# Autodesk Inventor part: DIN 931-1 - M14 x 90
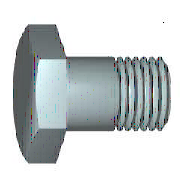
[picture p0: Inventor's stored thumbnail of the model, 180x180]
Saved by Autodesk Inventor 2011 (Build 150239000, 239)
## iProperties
Created: 2010-02
Part Number: DIN 931-1 - M14 x 90
Material: Steel, Mild
Description: Hex-Head Bolt
Document SubType Name: Modeling
Standard: DIN 931-1
Designer: PC
Standard Revision: 2001
Standards Organization: DIN
Language: en-US
Size Designation: M14 x 90
Categories: <MemberInstance><Categories><Category DisplayName="Fasteners" InternalName="e4da775c-781d-43d5-af7c-5136215cf5a6" Mnemonic="FSTN"><Category DisplayName="Bolts"
Density: 1 g/cm^3
IsCustomPart: 0
Author: PC
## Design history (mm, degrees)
workplane "Work Plane1"
revolve "Body" stored, may be unused: angle "d12" = 90 deg
sketch "Sketch2"
  geometry: L1 (0, 12.702)-(11, 6.351); L2 (11, 6.351)-(11, -6.351); L3 (11, -6.351)-(0, -12.702); L4 (0, -12.702)-(-11, -6.351); L5 (-11, -6.351)-(-11, 6.351); L6 (-11, 6.351)-(0, 12.702); 2 further points
  constraints: 12 end point, 1 coincident, 1 vertical, 11 other
  dimensions: "d11" = 22 distance between parallel lines of L5 L2 (= SW)
extrude "Head" join sketch "Sketch2" distance "d3" = 8.2 (= KOH - SD); taper "d4" = 0 deg
revolve "Chamfer1" stored, may be unused: angle "d21" = 90 deg
body "Solid1"
feature "Thread" dims "d15" = 34 (= GEL), "d16" = 0
chamfer "Chamfer2" distance "d6" = 1.2269 (= -0.5 x SPD + 0.5 x GD); stored, may be unused: second distance "d7" = 1.227 (computed from GUL), angle "d55" = 45 deg
sketch "Sketch1"
  geometry: L1 (0, 10.25)-(0, 7); L2 (56, 7)-(90, 7); L3 (90, 7)-(90, 0); L4 (90, 0)-(-0.6, 0); L5 (-18.72, 0)-(108.12, 0) reference; L6 (-0.6, 0)-(-0.6, 10.25); L7 (-0.6, 10.25)-(0, 10.25); L8 (56, 7)-(54.773, 7); L9 (54.773, 7)-(0, 7); L10 (0, -2.05)-(0, 12.3) reference
  constraints: 16 end point, 2 collinear, 2 perpendicular, 1 parallel
  dimensions: "d0" = 90 distance between parallel lines of L3 L1 (= NLG); "d1" = 34 distance from line of L2.start L3 (= GEL); "d2" = 14 diameter of L2 L4 (= GD); "d9" = 0.6001 distance between parallel lines of L6 L1 (computed from SD); "d10" = 20.5 diameter of L7 L4 (= SD2); "d13" = 1.227 distance of L2.start L8.end (computed from GAL); "d14" = 14 diameter of L9 L4 (= BDM)
sketch "Sketch4"
  geometry: L1 (-8.8, 11)-(-8.8, 12.702); L2 (-8.8, 12.702)-(-7.818, 12.702); L3 (-7.818, 12.702)-(-8.8, 11); L4 (-10.44, 0)-(1.04, 0) reference; L5 (-0.6, 12.702)-(-8.8, 12.702) reference; L6 (-8.8, 6.351)-(-8.8, 12.702) reference
  constraints: 6 end point, 2 collinear, 1 perpendicular, 1 vertical
  dimensions: "d5" = 30 deg angle of L3 L1 (= ANG1); "d19" = 22 diameter of L1.start L4 (= SW0)
other parameters: "NLG" = 90 [user parameter; used in 1 equation term], "GD" = 14 (= NND) [user parameter; used in 2 equation terms], "BDM" = 14 (= NND) [user parameter; used in 1 equation term], "KOH" = 8.8 [user parameter; used in 1 equation term], "GEL" = 34 [user parameter; used in 2 equation terms], "SW" = 22 [user parameter; used in 3 equation terms], "SW0" = 22 (= SW) [user parameter; used in 1 equation term], "SPD" = 11.5462 (= NND - 1.2269 x PTC) [user parameter; used in 1 equation term], "SD2" = 20.5 [user parameter; used in 1 equation term], "SD" = 0.6 [user parameter; used in 2 equation terms], "ANG1" = 30 deg [user parameter; used in 1 equation term], "GAL" = 1.2269 (= 0.61345 x PTC) [user parameter; used in 1 equation term], "GUL" = 1.2269 (= 0.61345 x PTC) [user parameter; used in 1 equation term], "d8" = 0, "RR" = 0.6 [user parameter], "d57" = 0, "d58" = 0, "TPU" = 5 (computed from PTC) [user parameter], "GD1" = 11.5462 (= THREADDIA - 1.2269 x PTC) [user parameter], "THREADDIA" = 14 [user parameter; used in 1 equation term], "TOA" = 30 deg [user parameter], "PTC" = 2 [user parameter; used in 5 equation terms], "NND" = 14 [user parameter; used in 3 equation terms], "E0" = 25.41 (= 1.155 x SW) [user parameter]
